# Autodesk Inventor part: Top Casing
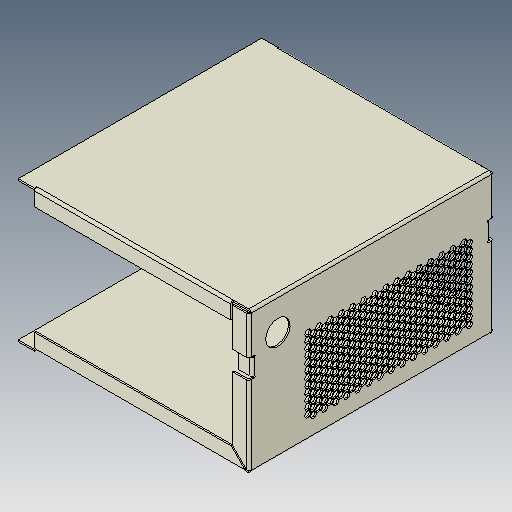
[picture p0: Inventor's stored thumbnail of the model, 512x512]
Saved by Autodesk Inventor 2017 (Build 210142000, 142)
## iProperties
Created: 2005-12
Part Number: Top Casing
Material: Generic
Document SubType Name: Modeling
Designer: DanielSeverino
Density: 1 g/cm^3
Appearance: Default
Author: DanielSeverino
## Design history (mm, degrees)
feature "Solid1"
body "Solid2"
